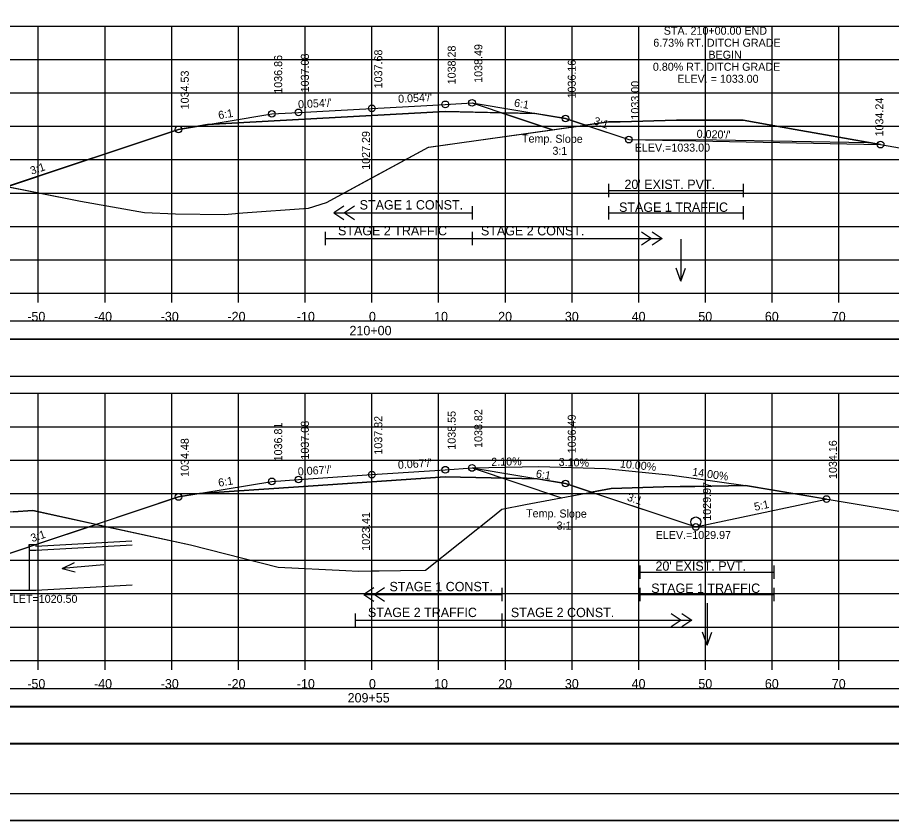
# Model space of a CAD drawing. Extents: x 1370565 to 1374448, y 301010 to 304637.
# Drawn here: x 1373315.7 to 1373446.7, y 301938.3 to 302058.6 of the extents above; entities that cross this region are included whole.
import ezdxf

# ---------------------------------------------------------------- set-up
doc = ezdxf.new("R2010")
doc.units = 0
for name, color, linetype in [('Default', 7, 'Continuous'), ('R_Alt Surface', 7, 'Continuous'), ('R_Axis', 7, 'Continuous'), ('R_Axis Annot', 7, 'Continuous'), ('R_Border', 7, 'Continuous'), ('R_Contours', 7, 'Continuous'), ('R_Drive', 7, 'Continuous'), ('R_Exist Surface', 7, 'Continuous'), ('R_Fin Surface', 7, 'Continuous'), ('R_Grid', 7, 'Continuous'), ('R_No Plot', 7, 'Continuous'), ('R_Water', 7, 'Continuous'), ('R_Water Annot', 7, 'Continuous'), ('R_Xsect Elev', 7, 'Continuous'), ('R_Xsect Slope', 7, 'Continuous')]:
    doc.layers.add(name, color=color, linetype=linetype)

msp = doc.modelspace()

# ---------------------------------------------------------------- linework, layer by layer
at = {"layer": 'Default'}
for points in [[(1373219.61, 301955.35), (1373518.02, 301955.35), (1373518.02, 301958.06), (1373219.61, 301958.06)], [(1373219.61, 301949.83), (1373518.02, 301949.83), (1373518.02, 301955.35), (1373219.61, 301955.35)]]:
    msp.add_lwpolyline(points, close=True, dxfattribs=at)
at = {"layer": 'R_Alt Surface'}
for points in [[(1373344.17, 302042.57), (1373357.81, 302043.31), (1373368.81, 302043.91), (1373379.81, 302044.51), (1373393.23, 302044.24)], [(1373364.61, 302030.36), (1373363.11, 302029.36), (1373364.61, 302028.36)], [(1373366.21, 302030.36), (1373364.71, 302029.36), (1373366.21, 302028.36)], [(1373363.11, 302029.36), (1373383.81, 302029.36)], [(1373361.81, 302026.49), (1373361.81, 302024.49)], [(1373383.81, 302026.49), (1373383.81, 302024.49)], [(1373383.81, 302026.49), (1373383.81, 302024.49)], [(1373409.21, 302026.49), (1373410.71, 302025.49), (1373409.21, 302024.49)], [(1373410.8, 302026.49), (1373412.3, 302025.49), (1373410.8, 302024.49)], [(1373361.81, 302025.49), (1373383.81, 302025.49)], [(1373383.81, 302025.49), (1373412.3, 302025.49)], [(1373342.95, 301987.31), (1373357.81, 301988.31), (1373368.81, 301989.05), (1373379.81, 301989.78), (1373393.57, 301989.51)], [(1373369.08, 301973.2), (1373367.58, 301972.2), (1373369.08, 301971.2)], [(1373370.68, 301973.2), (1373369.18, 301972.2), (1373370.68, 301971.2)], [(1373367.58, 301972.2), (1373388.29, 301972.2)], [(1373366.29, 301969.32), (1373366.29, 301967.32)], [(1373388.29, 301969.32), (1373388.29, 301967.32)], [(1373388.29, 301969.32), (1373388.29, 301967.32)], [(1373413.68, 301969.32), (1373415.18, 301968.32), (1373413.68, 301967.32)], [(1373415.28, 301969.32), (1373416.78, 301968.32), (1373415.28, 301967.32)], [(1373366.29, 301968.32), (1373388.29, 301968.32)], [(1373388.29, 301968.32), (1373416.78, 301968.32)]]:
    msp.add_lwpolyline(points, dxfattribs=at)
at = {"layer": 'R_Axis'}
for p, q in [((1373218.81, 302017.31), (1373518.81, 302017.31)), ((1373318.81, 302015.91), (1373318.81, 302017.31)), ((1373328.81, 302015.91), (1373328.81, 302017.31)), ((1373338.81, 302015.91), (1373338.81, 302017.31)), ((1373348.81, 302015.91), (1373348.81, 302017.31)), ((1373358.81, 302015.91), (1373358.81, 302017.31)), ((1373368.81, 302015.91), (1373368.81, 302017.31)), ((1373378.81, 302015.91), (1373378.81, 302017.31)), ((1373388.81, 302015.91), (1373388.81, 302017.31)), ((1373398.81, 302015.91), (1373398.81, 302017.31)), ((1373408.81, 302015.91), (1373408.81, 302017.31)), ((1373418.81, 302015.91), (1373418.81, 302017.31)), ((1373428.81, 302015.91), (1373428.81, 302017.31)), ((1373438.81, 302015.91), (1373438.81, 302017.31)), ((1373218.81, 301962.31), (1373518.81, 301962.31)), ((1373318.81, 301960.91), (1373318.81, 301962.31)), ((1373328.81, 301960.91), (1373328.81, 301962.31)), ((1373338.81, 301960.91), (1373338.81, 301962.31)), ((1373348.81, 301960.91), (1373348.81, 301962.31)), ((1373358.81, 301960.91), (1373358.81, 301962.31)), ((1373368.81, 301960.91), (1373368.81, 301962.31)), ((1373378.81, 301960.91), (1373378.81, 301962.31)), ((1373388.81, 301960.91), (1373388.81, 301962.31)), ((1373398.81, 301960.91), (1373398.81, 301962.31)), ((1373408.81, 301960.91), (1373408.81, 301962.31)), ((1373418.81, 301960.91), (1373418.81, 301962.31)), ((1373428.81, 301960.91), (1373428.81, 301962.31)), ((1373438.81, 301960.91), (1373438.81, 301962.31))]:
    msp.add_line(p, q, dxfattribs=at)
for points in [[(1373404.25, 302033.67), (1373404.25, 302031.67)], [(1373404.25, 302032.67), (1373424.46, 302032.67)], [(1373424.46, 302033.67), (1373424.46, 302031.67)], [(1373383.81, 302030.36), (1373383.81, 302028.36)], [(1373404.25, 302030.36), (1373404.25, 302028.36)], [(1373424.46, 302030.36), (1373424.46, 302028.36)], [(1373404.25, 302029.36), (1373424.46, 302029.36)], [(1373408.96, 301976.51), (1373408.96, 301974.51)], [(1373429.04, 301976.51), (1373429.04, 301974.51)], [(1373408.96, 301975.51), (1373429.04, 301975.51)], [(1373388.29, 301973.2), (1373388.29, 301971.2)], [(1373408.96, 301973.2), (1373408.96, 301971.2)], [(1373429.04, 301973.2), (1373429.04, 301971.2)], [(1373408.96, 301972.2), (1373429.04, 301972.2)]]:
    msp.add_lwpolyline(points, dxfattribs=at)
at = {"layer": 'R_Border'}
msp.add_line((1373526.99, 301942.31), (1373210.81, 301942.31), dxfattribs=at)
at = {"layer": 'R_Contours'}
for p, q in [((1373395.89, 302041.78), (1373388.22, 302044.34)), ((1373393.23, 302044.24), (1373388.22, 302044.34)), ((1373388.22, 302044.34), (1373395.89, 302041.78)), ((1373400.82, 302042.47), (1373407.3, 302040.31)), ((1373407.3, 302040.31), (1373445.05, 302039.56)), ((1373436.94, 301986.48), (1373424.81, 301988.48)), ((1373318.43, 301979.66), (1373327.48, 301982.68)), ((1373317.43, 301979.66), (1373318.43, 301979.66)), ((1373317.43, 301979.33), (1373317.43, 301979.66))]:
    msp.add_line(p, q, dxfattribs=at)
for points in [[(1373388.22, 302044.34), (1373379.81, 302044.51), (1373368.81, 302043.91), (1373357.81, 302043.31), (1373344.17, 302042.57)], [(1373400.82, 302042.47), (1373397.81, 302043.47), (1373393.23, 302044.24)], [(1373445.05, 302039.56), (1373432.26, 302041.81), (1373424.46, 302043.23), (1373422.82, 302043.23), (1373414.44, 302043.2), (1373406.02, 302042.99), (1373404.25, 302042.95), (1373400.82, 302042.47)], [(1373344.17, 302042.57), (1373339.81, 302041.84), (1373314.14, 302033.28)], [(1373395.89, 302041.78), (1373395.89, 302041.78), (1373400.82, 302042.47)], [(1373314.14, 302033.28), (1373325.16, 302031.07), (1373334.75, 302029.37), (1373339.38, 302029.2), (1373346.74, 302029.08), (1373349.44, 302029.34), (1373359.32, 302030.03), (1373362, 302030.91), (1373368.81, 302034.6), (1373377.28, 302039.18), (1373395.89, 302041.78)], [(1373393.57, 301989.51), (1373379.81, 301989.78), (1373368.81, 301989.05), (1373357.81, 301988.31), (1373342.95, 301987.31)], [(1373401.73, 301987.5), (1373397.81, 301988.8), (1373393.57, 301989.51)], [(1373424.81, 301988.48), (1373417.23, 301988.37), (1373415, 301988.36), (1373412.57, 301988.3), (1373404.66, 301988.04), (1373401.73, 301987.5)], [(1373342.95, 301987.31), (1373342.95, 301987.31), (1373339.81, 301986.79), (1373327.48, 301982.68)], [(1373373.09, 301975.78), (1373376.86, 301975.82), (1373387.15, 301984.02), (1373388.28, 301984.96), (1373391.85, 301985.67), (1373401.73, 301987.5)], [(1373401.73, 301987.5), (1373417.36, 301982.29), (1373436.94, 301986.48)], [(1373327.48, 301982.68), (1373317.98, 301984.74), (1373315.03, 301984.58), (1373287.35, 301983.75), (1373274.03, 301983.15), (1373267.7, 301982.87)], [(1373267.7, 301982.87), (1373297.88, 301972.81), (1373302.93, 301974.5), (1373317.43, 301979.33)], [(1373327.48, 301982.68), (1373341.6, 301979.62), (1373354.77, 301976.29), (1373364.92, 301975.77), (1373366.74, 301975.69), (1373368.81, 301975.72), (1373373.09, 301975.78)]]:
    msp.add_lwpolyline(points, dxfattribs=at)
msp.add_lwpolyline([(1373219.61, 301949.89), (1373518.02, 301949.89), (1373518.02, 301955.41), (1373219.61, 301955.41)], close=True, dxfattribs=at)
at = {"layer": 'R_Drive'}
for p, q in [((1373383.81, 301991.13), (1373393.81, 301991.34)), ((1373393.81, 301991.34), (1373403.81, 301991.03)), ((1373403.81, 301991.03), (1373413.81, 301990.03)), ((1373413.81, 301990.03), (1373424.81, 301988.48))]:
    msp.add_line(p, q, dxfattribs=at)
for points in [[(1373219.61, 302010.41), (1373518.02, 302010.41), (1373518.02, 302013.11), (1373219.61, 302013.11)], [(1373219.61, 302004.89), (1373518.02, 302004.89), (1373518.02, 302010.41), (1373219.61, 302010.41)]]:
    msp.add_lwpolyline(points, close=True, dxfattribs=at)
at = {"layer": 'R_Exist Surface'}
for points in [[(1373312.99, 302033.51), (1373325.16, 302031.07), (1373334.75, 302029.37), (1373339.38, 302029.2), (1373346.74, 302029.08), (1373349.44, 302029.34), (1373359.32, 302030.03), (1373362, 302030.91), (1373377.28, 302039.18), (1373377.36, 302039.19), (1373404.25, 302042.95), (1373406.02, 302042.99), (1373414.44, 302043.2), (1373422.82, 302043.23), (1373424.46, 302043.23), (1373432.26, 302041.81), (1373451.59, 302038.41), (1373459.97, 302038.57), (1373469.44, 302038.63), (1373498.38, 302039.55), (1373518.81, 302040.41)], [(1373315.03, 301984.58), (1373317.98, 301984.74), (1373341.6, 301979.62), (1373354.77, 301976.29), (1373364.92, 301975.77), (1373366.74, 301975.69), (1373373.09, 301975.78), (1373376.86, 301975.82), (1373387.15, 301984.02), (1373388.28, 301984.96), (1373391.85, 301985.67), (1373404.66, 301988.04), (1373412.57, 301988.3), (1373415, 301988.36), (1373417.23, 301988.37), (1373424.81, 301988.48), (1373448.45, 301984.58), (1373449.95, 301984.33), (1373465.18, 301984.57), (1373469.25, 301984.63), (1373471.45, 301984.72), (1373517.94, 301986.93), (1373518.81, 301986.96)]]:
    msp.add_lwpolyline(points, dxfattribs=at)
at = {"layer": 'R_Fin Surface'}
for p, q in [((1373383.81, 302045.81), (1373395.89, 302041.78)), ((1373383.81, 301991.13), (1373397.23, 301986.66))]:
    msp.add_line(p, q, dxfattribs=at)
for points in [[(1373268.02, 302037.71), (1373297.73, 302027.81), (1373339.81, 302041.84), (1373353.81, 302044.18), (1373357.81, 302044.39), (1373368.81, 302044.99), (1373379.81, 302045.59), (1373383.81, 302045.81), (1373397.81, 302043.47), (1373407.3, 302040.31), (1373420.47, 302040.28), (1373443.15, 302039.89), (1373443.6, 302039.81), (1373445.05, 302039.56)], [(1373267.7, 301982.87), (1373267.7, 301982.87), (1373297.88, 301972.81), (1373339.81, 301986.79), (1373339.81, 301986.79), (1373353.81, 301989.12), (1373357.81, 301989.39), (1373368.81, 301990.13), (1373379.81, 301990.87), (1373383.81, 301991.13), (1373397.81, 301988.8), (1373417.36, 301982.29), (1373436.94, 301986.48)]]:
    msp.add_lwpolyline(points, dxfattribs=at)
at = {"layer": 'R_Grid'}
for p, q in [((1373218.81, 302057.31), (1373518.81, 302057.31)), ((1373318.81, 302017.31), (1373318.81, 302057.31)), ((1373328.81, 302017.31), (1373328.81, 302057.31)), ((1373338.81, 302017.31), (1373338.81, 302057.31)), ((1373348.81, 302017.31), (1373348.81, 302057.31)), ((1373358.81, 302017.31), (1373358.81, 302057.31)), ((1373368.81, 302017.31), (1373368.81, 302057.31)), ((1373378.81, 302017.31), (1373378.81, 302057.31)), ((1373388.81, 302017.31), (1373388.81, 302057.31)), ((1373398.81, 302017.31), (1373398.81, 302057.31)), ((1373408.81, 302017.31), (1373408.81, 302057.31)), ((1373418.81, 302017.31), (1373418.81, 302057.31)), ((1373428.81, 302017.31), (1373428.81, 302057.31)), ((1373438.81, 302017.31), (1373438.81, 302057.31)), ((1373218.81, 302052.31), (1373518.81, 302052.31)), ((1373218.81, 302047.31), (1373518.81, 302047.31)), ((1373218.81, 302042.31), (1373518.81, 302042.31)), ((1373218.81, 302037.31), (1373518.81, 302037.31)), ((1373218.81, 302032.31), (1373518.81, 302032.31)), ((1373218.81, 302027.31), (1373518.81, 302027.31)), ((1373218.81, 302022.31), (1373518.81, 302022.31)), ((1373218.81, 302017.31), (1373518.81, 302017.31)), ((1373218.81, 302002.31), (1373518.81, 302002.31)), ((1373318.81, 301962.31), (1373318.81, 302002.31)), ((1373328.81, 301962.31), (1373328.81, 302002.31)), ((1373338.81, 301962.31), (1373338.81, 302002.31)), ((1373348.81, 301962.31), (1373348.81, 302002.31)), ((1373358.81, 301962.31), (1373358.81, 302002.31)), ((1373368.81, 301962.31), (1373368.81, 302002.31)), ((1373378.81, 301962.31), (1373378.81, 302002.31)), ((1373388.81, 301962.31), (1373388.81, 302002.31)), ((1373398.81, 301962.31), (1373398.81, 302002.31)), ((1373408.81, 301962.31), (1373408.81, 302002.31)), ((1373418.81, 301962.31), (1373418.81, 302002.31)), ((1373428.81, 301962.31), (1373428.81, 302002.31)), ((1373438.81, 301962.31), (1373438.81, 302002.31)), ((1373218.81, 301997.31), (1373518.81, 301997.31)), ((1373218.81, 301992.31), (1373518.81, 301992.31)), ((1373218.81, 301987.31), (1373518.81, 301987.31)), ((1373218.81, 301982.31), (1373518.81, 301982.31)), ((1373218.81, 301977.31), (1373518.81, 301977.31)), ((1373218.81, 301972.31), (1373518.81, 301972.31)), ((1373218.81, 301967.31), (1373518.81, 301967.31)), ((1373218.81, 301962.31), (1373518.81, 301962.31))]:
    msp.add_line(p, q, dxfattribs=at)
at = {"layer": 'R_No Plot'}
msp.add_line((1373198.41, 301938.33), (1373531.75, 301938.33), dxfattribs=at)
for points in [[(1373198.41, 302151.67), (1373531.75, 302151.67), (1373531.75, 301938.33), (1373198.41, 301938.33)], [(1373444.73, 302147.77), (1373464.35, 302147.77), (1373464.35, 302137.89), (1373480.47, 302137.89), (1373503.67, 302137.89), (1373503.67, 302105.22), (1373526.87, 302105.22), (1373526.99, 301942.31), (1373210.81, 301942.31), (1373210.81, 302147.77)]]:
    msp.add_lwpolyline(points, close=True, dxfattribs=at)
for centre in [(1373379.81, 302045.59), (1373383.81, 302045.81), (1373353.81, 302044.18), (1373357.81, 302044.39), (1373368.81, 302044.99), (1373397.81, 302043.47), (1373339.81, 302041.84), (1373407.3, 302040.31), (1373445.05, 302039.56), (1373379.81, 301990.87), (1373383.81, 301991.13), (1373353.81, 301989.12), (1373357.81, 301989.39), (1373368.81, 301990.13), (1373397.81, 301988.8), (1373339.81, 301986.79), (1373436.94, 301986.48), (1373417.36, 301982.29)]:
    msp.add_circle(centre, 0.5, dxfattribs=at)
at = {"layer": 'R_Water'}
for p, q in [((1373317.43, 301979.66), (1373317.43, 301972.81)), ((1373317.43, 301979.66), (1373318.43, 301979.66)), ((1373318.43, 301979.41), (1373332.85, 301980.2)), ((1373318.43, 301979.66), (1373318.43, 301979.41)), ((1373318.43, 301978.81), (1373332.88, 301979.61)), ((1373317.43, 301978.81), (1373318.43, 301978.81)), ((1373297.88, 301972.81), (1373318.43, 301972.81)), ((1373318.43, 301972.81), (1373332.88, 301973.61))]:
    msp.add_line(p, q, dxfattribs=at)
msp.add_circle((1373417.36, 301983.04), 0.75, dxfattribs=at)
at = {"layer": 'R_Water Annot'}
for p, q in [((1373415.11, 302025.4), (1373415.11, 302019.12)), ((1373415.11, 302019.12), (1373414.42, 302021.04)), ((1373415.11, 302019.12), (1373415.79, 302021.04)), ((1373322.38, 301976.09), (1373324.24, 301976.96)), ((1373328.65, 301976.63), (1373322.38, 301976.09)), ((1373322.38, 301976.09), (1373324.36, 301975.56)), ((1373419.03, 301970.88), (1373419.03, 301964.59)), ((1373419.03, 301964.59), (1373418.33, 301966.52)), ((1373419.03, 301964.59), (1373419.73, 301966.52))]:
    msp.add_line(p, q, dxfattribs=at)
at = {"layer": 'R_Xsect Elev'}
for p, q in [((1373368.81, 302034.6), (1373368.81, 302042.21)), ((1373368.81, 301975.72), (1373368.81, 301985.72))]:
    msp.add_line(p, q, dxfattribs=at)

# ---------------------------------------------------------------- texts
at = {"layer": 'R_Axis Annot'}
for s, p in [("20' EXIST. PVT.", (1373406.66, 302032.91)), ('-50', (1373317.16, 302013.11)), ('-40', (1373327.16, 302013.11)), ('-30', (1373337.16, 302013.11)), ('-20', (1373347.16, 302013.11)), ('-10', (1373357.55, 302013.11)), ('0', (1373368.36, 302013.11)), ('10', (1373378.13, 302013.11)), ('20', (1373387.73, 302013.11)), ('30', (1373397.73, 302013.11)), ('40', (1373407.73, 302013.11)), ('50', (1373417.73, 302013.11)), ('60', (1373427.7, 302013.11)), ('70', (1373437.73, 302013.11)), ('210+00', (1373365.45, 302011.01)), ("20' EXIST. PVT.", (1373411.31, 301975.74)), ('-50', (1373317.16, 301958.11)), ('-40', (1373327.16, 301958.11)), ('-30', (1373337.16, 301958.11)), ('-20', (1373347.16, 301958.11)), ('-10', (1373357.55, 301958.11)), ('0', (1373368.36, 301958.11)), ('10', (1373378.13, 301958.11)), ('20', (1373387.73, 301958.11)), ('30', (1373397.73, 301958.11)), ('40', (1373407.73, 301958.11)), ('50', (1373417.73, 301958.11)), ('60', (1373427.7, 301958.11)), ('70', (1373437.73, 301958.11)), ('209+55', (1373365.17, 301956.01))]:
    msp.add_text(s, height=1.4, dxfattribs=at).set_placement(p)
at = {"layer": 'R_Water'}
for s, p in [('STAGE 1 CONST.', (1373366.97, 302029.84)), ('STAGE 1 TRAFFIC', (1373405.85, 302029.49)), ('STAGE 2 TRAFFIC', (1373363.73, 302025.97)), ('STAGE 2 CONST.', (1373385.15, 302025.96)), ('STAGE 1 CONST.', (1373371.44, 301972.67)), ('STAGE 1 TRAFFIC', (1373410.67, 301972.42)), ('STAGE 2 TRAFFIC', (1373368.21, 301968.8)), ('STAGE 2 CONST.', (1373389.63, 301968.79))]:
    msp.add_text(s, height=1.4, dxfattribs=at).set_placement(p)
at = {"layer": 'R_Water Annot'}
msp.add_text('F.L. OUTLET=1020.50', height=1.2, dxfattribs=at).set_placement((1373308.4, 301970.93))
at = {"layer": 'R_Xsect Elev'}
for s, p in [('STA. 210+00.00 END', (1373412.55, 302056.02)), ('6.73% RT. DITCH GRADE', (1373410.98, 302054.22)), ('BEGIN', (1373419.24, 302052.42)), ('0.80% RT. DITCH GRADE', (1373410.92, 302050.62)), ('ELEV. = 1033.00', (1373414.58, 302048.82)), ('ELEV.=1033.00', (1373408.2, 302038.51)), ('ELEV.=1029.97', (1373411.34, 301980.49))]:
    msp.add_text(s, height=1.2, dxfattribs=at).set_placement(p)
for s, rotation, p in [('1037.68', 90, (1373370.36, 302047.99)), ('1038.28', 90, (1373381.36, 302048.59)), ('1038.49', 90, (1373385.36, 302048.81)), ('1036.86', 90, (1373355.36, 302047.18)), ('1037.08', 90, (1373359.36, 302047.39)), ('1036.16', 90, (1373399.36, 302046.47)), ('1034.53', 90, (1373341.36, 302044.84)), ('1033.00', 90, (1373408.85, 302043.31)), ('1034.24', 90, (1373445.46, 302040.78)), ('1027.29', 90, (1373368.51, 302035.79)), ('1037.82', 90, (1373370.36, 301993.13)), ('1038.55', 90, (1373381.36, 301993.87)), ('1038.82', 90, (1373385.36, 301994.13)), ('1036.49', 90, (1373399.36, 301993.33)), ('1036.81', 90, (1373355.36, 301992.12)), ('1037.08', 90, (1373359.36, 301992.39)), ('1034.48', 90, (1373341.36, 301989.79)), ('1034.16', 90, (1373438.49, 301989.48)), ('2.10%', 1.203, (1373386.71, 301991.44)), ('3.10%', 358.2244, (1373396.79, 301991.44)), ('10.00%', 354.2894, (1373405.94, 301991.21)), ('14.00%', 352.0304, (1373416.76, 301989.99)), ('1029.97', 90, (1373419.62, 301983.23)), ('1023.41', 90, (1373368.51, 301978.72))]:
    msp.add_text(s, height=1.2, rotation=rotation, dxfattribs=at).set_placement(p)
at = {"layer": 'R_Xsect Slope'}
for s, rotation, p in [("0.054'/'", 3.1124, (1373372.77, 302045.81)), ("0.054'/'", 3.1124, (1373357.77, 302044.99)), ('6:1', 350.5377, (1373390.05, 302045.27)), ('6:1', 9.4623, (1373345.88, 302043.36)), ('3:1', 341.5651, (1373401.92, 302042.63)), ('Temp. Slope ', 359.5466, (1373391.3, 302039.88)), ("0.020'/'", 358.2452, (1373417.46, 302040.59)), ('3:1', 359.5466, (1373395.86, 302038.04)), ('3:1', 18.4349, (1373317.82, 302035.04)), ("0.067'/'", 3.8317, (1373372.74, 301990.99)), ("0.067'/'", 3.8317, (1373357.74, 301989.99)), ('6:1', 350.5377, (1373393.32, 301989.73)), ('6:1', 9.4623, (1373345.88, 301988.31)), ('3:1', 341.5651, (1373406.96, 301986.28)), ('5:1', 12.0791, (1373426.23, 301984.7)), ('Temp. Slope ', 359.5466, (1373391.91, 301983.75)), ('3:1', 359.5466, (1373396.48, 301981.91)), ('3:1', 18.4349, (1373317.9, 301980.01))]:
    msp.add_text(s, height=1.2, rotation=rotation, dxfattribs=at).set_placement(p)

doc.saveas('drawing.dxf')
